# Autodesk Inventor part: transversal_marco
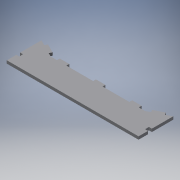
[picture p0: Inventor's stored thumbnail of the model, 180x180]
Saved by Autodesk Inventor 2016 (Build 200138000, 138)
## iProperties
Created: 2017-06
Part Number: transversal_marco
Material: Generic
Document SubType Name: Modeling
Designer: laboratorioesan
Density: 1 g/cm^3
Appearance: Default
Author: laboratorioesan
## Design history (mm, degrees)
sketch "Sketch1"
  geometry: L1 (0, 0)-(0, -60) reference; L2 (0, 0)-(-18.5, 0) reference; L3 (-18.5, -60)-(-18.5, 0) reference; L4 (818.5, 0)-(818.5, -60) reference; L5 (818.5, 0)-(800, 0) reference; L6 (800, -60)-(800, 0) reference; L7 (-18.5, 24.5)-(0, 24.5) reference; L8 (800, 24.5)-(818.5, 24.5) reference; L9 (800, 24.5)-(800, -3) reference; L10 (0, 24.5)-(0, -3) reference; L11 (-18.5, -60)-(818.5, -60); L12 (818.5, -60)-(818.5, 0); L13 (818.5, 0)-(800, 0); L14 (800, 0)-(800, 24.5); L15 (800, 24.5)-(818.5, 24.5); L16 (-18.5, -60)-(-18.5, 0); L17 (-18.5, 0)-(0, 0); L18 (0, 0)-(0, 24.5); L19 (0, 24.5)-(-18.5, 24.5); L20 (818.5, 24.5)-(818.5, 100); L21 (-18.5, 24.5)-(-18.5, 100); L22 (-18.5, 100)-(818.5, 100); L23 (140, 100)-(200, 100); L24 (200, 100)-(200, 118); L25 (200, 118)-(140, 118); L26 (140, 118)-(140, 100); L27 (370, 100)-(430, 100); L28 (430, 100)-(430, 118); L29 (430, 118)-(370, 118); L30 (370, 118)-(370, 100); L31 (600, 100)-(660, 100); L32 (660, 100)-(660, 118); L33 (660, 118)-(600, 118); L34 (600, 118)-(600, 100); L35 (-18.5, 100)-(-18.5, 160); L36 (-18.5, 160)-(100, 100); L37 (818.5, 100)-(818.5, 160); L38 (818.5, 160)-(700, 100); L39 (17.186, 141.931)-(25.317, 157.99); L40 (25.317, 157.99)-(83.308, 128.628); L41 (83.308, 128.628)-(75.177, 112.569); L42 (400, 100)-(400, 38.349); L43 (716.692, 128.628)-(724.823, 112.569); L44 (774.683, 157.99)-(716.692, 128.628); L45 (782.814, 141.931)-(774.683, 157.99); L46 (724.823, 112.569)-(716.692, 128.628); L47 (716.692, 128.628)-(774.683, 157.99); L48 (774.683, 157.99)-(782.814, 141.931); L49 (782.814, 141.931)-(724.823, 112.569); L50 (0, -60)-(-18.5, -60) reference; L51 (818.5, -60)-(800, -60) reference; 1 further point
  constraints: 78 end point, 11 perpendicular, 9 point on line, 7 parallel, 6 collinear, 4 symmetric about line, 4 vertical, 3 horizontal, 2 horizontal alignment, 2 midpoint, 1 vertical alignment
  dimensions: "d0" = 75.5 distance of L8.end L20.end; "d1" = 18 distance of L23.end L24.end; "d2" = 60 distance of L24.end L25.end; "d3" = 170 distance of L29.end L24.end; "d4" = 170 distance of L33.end L28.end; "d5" = 60 distance of L21.end L35.end; "d6" = 40 distance of L23.start L36.end; "d8" = 40 distance of L38.end L31.end; "d9" = 65 distance of L39.end L40.end; "d10" = 18 distance of L39.start L39.end; "d11" = 40 distance of L35.end L39.start
extrude "Extrusion1" new body sketch "Sketch1" distance "d12" = 18.5; taper "d13" = 0 deg
body "Solid1"
node "Reference1"
node "Reference2"
node "Reference3"
node "Reference4"
node "Reference5"
node "Reference6"
